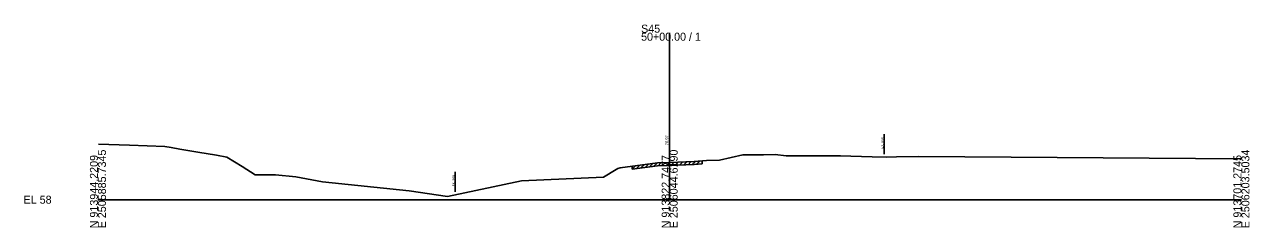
# Model space of a CAD drawing. Extents: x -26 to 403, y -10 to 17520.
# Drawn here: x -25.7 to 402.8, y 11990.3 to 12061.1 of the extents above; entities that cross this region are included whole.
import ezdxf

# ---------------------------------------------------------------- set-up
doc = ezdxf.new("R2010")
doc.units = 0
for name, color, linetype in [('RD_GPK_XS_Cell', 7, 'Continuous'), ('RD_XS_ExGround', 7, 'Continuous'), ('RD_XS_ExPaveRet', 7, 'Continuous'), ('RD_XS_ExRW', 7, 'Continuous'), ('RD_XS_TX_Elev_EX', 7, 'Continuous')]:
    doc.layers.add(name, color=color, linetype=linetype)

msp = doc.modelspace()

# ---------------------------------------------------------------- linework, layer by layer
at = {"layer": 'RD_GPK_XS_Cell'}
for p, q in [((200, 12000), (200, 12058.29)), ((0, 12000), (200, 12000)), ((200, 12000), (400, 12000))]:
    msp.add_line(p, q, dxfattribs=at)
at = {"layer": 'RD_XS_ExGround'}
for p, q in [((0.2, 12019.43), (11.03, 12019.04)), ((11.03, 12019.04), (23.43, 12018.59)), ((23.43, 12018.59), (25.57, 12018.18)), ((25.57, 12018.18), (28.7, 12017.68)), ((28.7, 12017.68), (34.98, 12016.61)), ((34.98, 12016.61), (41.46, 12015.55)), ((41.46, 12015.55), (45.03, 12014.85)), ((45.03, 12014.85), (50.49, 12011.59)), ((182.63, 12011.11), (195.69, 12012.81)), ((195.69, 12012.81), (200, 12012.97)), ((200, 12012.97), (208.55, 12013.29)), ((208.55, 12013.29), (212.88, 12013.68)), ((212.88, 12013.68), (217.48, 12013.84)), ((217.48, 12013.84), (225.56, 12015.62)), ((225.56, 12015.62), (232.84, 12015.65)), ((232.84, 12015.65), (236.87, 12015.73)), ((236.87, 12015.73), (240.75, 12015.36)), ((240.75, 12015.36), (259.72, 12015.25)), ((259.72, 12015.25), (263.42, 12015.17)), ((263.42, 12015.17), (270.82, 12014.93)), ((270.82, 12014.93), (275.75, 12014.89)), ((275.75, 12014.89), (279.3, 12014.96)), ((279.3, 12014.96), (287.12, 12015.07)), ((287.12, 12015.07), (400, 12014.31)), ((50.49, 12011.59), (54.99, 12008.72)), ((54.99, 12008.72), (62.11, 12008.66)), ((62.11, 12008.66), (69.19, 12008.01)), ((69.19, 12008.01), (78.51, 12006.24)), ((148.16, 12006.6), (176.81, 12007.89)), ((176.81, 12007.89), (181.3, 12010.54)), ((181.3, 12010.54), (181.89, 12010.94)), ((181.89, 12010.94), (182.63, 12011.11)), ((78.51, 12006.24), (108.86, 12003.04)), ((122.24, 12001.14), (148.16, 12006.6)), ((108.86, 12003.04), (122.24, 12001.14))]:
    msp.add_line(p, q, dxfattribs=at)
at = {"layer": 'RD_XS_ExPaveRet'}
for p, q in [((186.93, 12010.67), (188.07, 12011.82)), ((186.93, 12010.67), (195.69, 12011.81)), ((188.43, 12010.87), (189.57, 12012.02)), ((189.93, 12011.06), (191.07, 12012.21)), ((191.43, 12011.26), (192.57, 12012.41)), ((192.93, 12011.45), (194.07, 12012.6)), ((194.43, 12011.65), (195.57, 12012.8)), ((195.69, 12011.81), (200, 12011.97)), ((195.93, 12011.82), (196.96, 12012.86)), ((197.43, 12011.88), (198.46, 12012.91)), ((198.93, 12011.93), (199.96, 12012.97)), ((200, 12011.97), (208.55, 12012.29)), ((200.43, 12011.99), (201.46, 12013.03)), ((201.93, 12012.04), (202.96, 12013.08)), ((203.43, 12012.1), (204.46, 12013.14)), ((204.93, 12012.15), (205.96, 12013.19)), ((206.43, 12012.21), (207.46, 12013.25)), ((207.93, 12012.26), (208.99, 12013.33)), ((208.55, 12012.29), (211.34, 12012.54)), ((209.43, 12012.37), (210.52, 12013.46)), ((211.34, 12013.54), (211.34, 12012.54)), ((186.93, 12010.67), (186.93, 12011.67))]:
    msp.add_line(p, q, dxfattribs=at)
at = {"layer": 'RD_XS_ExRW'}
for p, q in [((275, 12015.89), (275, 12022.89)), ((125, 12002.72), (125, 12009.72))]:
    msp.add_line(p, q, dxfattribs=at)

# ---------------------------------------------------------------- texts
at = {"layer": 'RD_GPK_XS_Cell'}
for s, p in [('S45', (190, 12058.29)), ('50+00.00 / 1', (190, 12055.49)), ('EL 58', (-26, 11998.6))]:
    msp.add_text(s, height=2.8, dxfattribs=at).set_placement(p)
for s, p in [('E 2505885.7345', (2.8, 11990)), ('E 2506044.6190', (202.8, 11990)), ('E 2506203.5034', (402.8, 11990)), ('N 913944.2209', (0, 11990)), ('N 913822.7477', (200, 11990)), ('N 913701.2745', (400, 11990))]:
    msp.add_text(s, height=2.8, rotation=90, dxfattribs=at).set_placement(p)
at = {"layer": 'RD_XS_ExRW'}
for p in [(274.75, 12017.85), (124.75, 12004.67)]:
    msp.add_text('EX. R/W ', height=0.75, rotation=90, dxfattribs=at).set_placement(p)
at = {"layer": 'RD_XS_TX_Elev_EX'}
msp.add_text('70.97', height=1, rotation=90, dxfattribs=at).set_placement((199.5, 12019.01))

doc.saveas('drawing.dxf')
